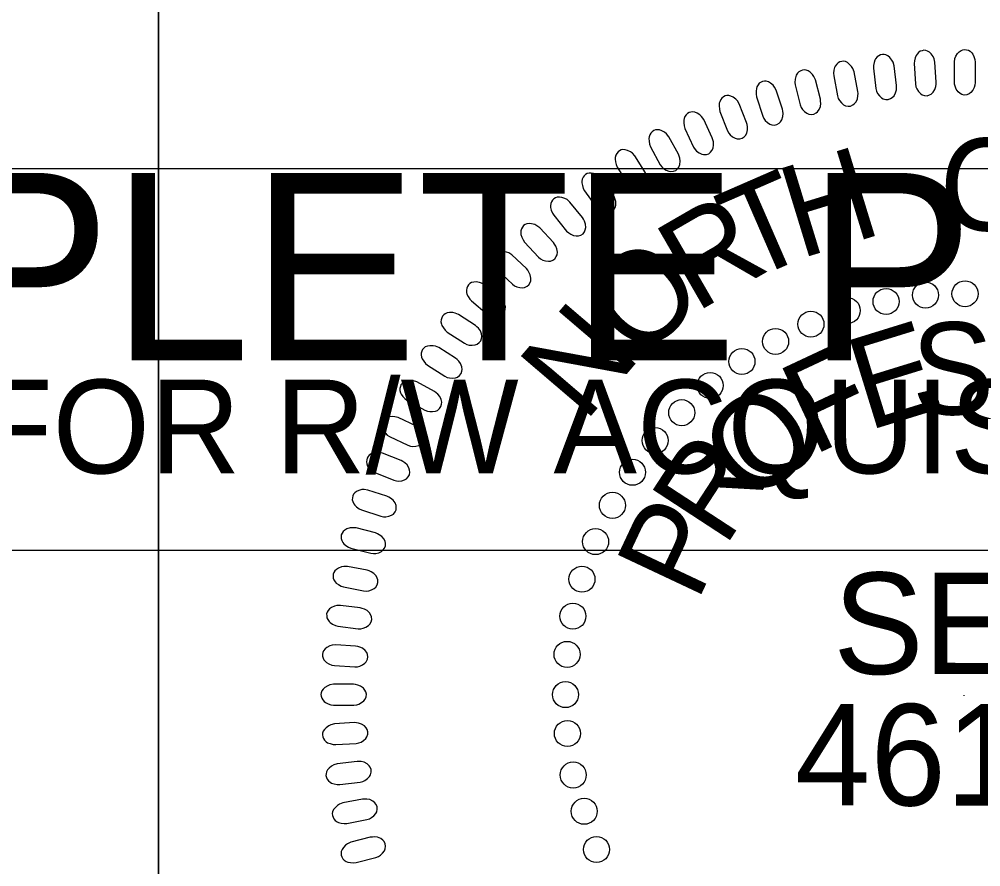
# Model space of a CAD drawing. Extents: x 505602 to 507548, y 483109 to 484209.
# Drawn here: x 507160.5 to 507219.7, y 484083.1 to 484135.2 of the extents above; entities that cross this region are included whole.
import ezdxf

# ---------------------------------------------------------------- set-up
doc = ezdxf.new("R2010")
doc.units = 0
for name, color, linetype in [('Sheet PE Seal Cell', 7, 'Continuous'), ('Sheet Profile CELL', 7, 'Continuous'), ('Sheet Sticker Incomplete CELL', 7, 'Continuous')]:
    doc.layers.add(name, color=color, linetype=linetype)

msp = doc.modelspace()

# ---------------------------------------------------------------- linework, layer by layer
at = {"layer": 'Sheet PE Seal Cell'}
msp.add_line((507218.627, 484093.626), (507218.627, 484093.58), dxfattribs=at)
for points in [[(507214.482, 484131.1), (507214.328, 484132.317), (507214.264, 484132.531), (507214.194, 484132.662), (507214.062, 484132.817), (507213.952, 484132.913), (507213.831, 484132.978), (507213.722, 484133.005), (507213.608, 484133.011), (507213.499, 484132.977), (507213.384, 484132.932), (507213.288, 484132.86), (507213.196, 484132.748), (507213.147, 484132.661), (507213.099, 484132.504), (507213.062, 484132.319), (507213.06, 484132.158), (507213.21, 484130.91), (507213.253, 484130.745), (507213.315, 484130.612), (507213.424, 484130.464), (507213.553, 484130.34), (507213.659, 484130.273), (507213.822, 484130.233), (507213.973, 484130.232), (507214.116, 484130.29), (507214.214, 484130.353), (507214.328, 484130.468), (507214.425, 484130.651), (507214.469, 484130.837), (507214.483, 484130.97)], [(507216.92, 484131.303), (507216.843, 484132.527), (507216.792, 484132.744), (507216.731, 484132.88), (507216.609, 484133.043), (507216.505, 484133.146), (507216.388, 484133.218), (507216.281, 484133.252), (507216.168, 484133.264), (507216.057, 484133.237), (507215.94, 484133.2), (507215.839, 484133.134), (507215.741, 484133.028), (507215.687, 484132.945), (507215.628, 484132.791), (507215.58, 484132.608), (507215.568, 484132.448), (507215.639, 484131.193), (507215.671, 484131.025), (507215.725, 484130.889), (507215.824, 484130.735), (507215.945, 484130.603), (507216.047, 484130.529), (507216.208, 484130.479), (507216.358, 484130.468), (507216.505, 484130.518), (507216.606, 484130.574), (507216.727, 484130.682), (507216.835, 484130.858), (507216.891, 484131.042), (507216.913, 484131.173)], [(507218.035, 484131.312), (507218.035, 484132.539), (507218.073, 484132.758), (507218.126, 484132.898), (507218.238, 484133.067), (507218.335, 484133.177), (507218.447, 484133.257), (507218.551, 484133.297), (507218.664, 484133.317), (507218.776, 484133.296), (507218.896, 484133.267), (507219, 484133.207), (507219.105, 484133.107), (507219.165, 484133.027), (507219.232, 484132.877), (507219.292, 484132.698), (507219.314, 484132.538), (507219.321, 484131.282), (507219.299, 484131.112), (507219.253, 484130.973), (507219.164, 484130.813), (507219.052, 484130.673), (507218.954, 484130.594), (507218.797, 484130.534), (507218.648, 484130.514), (507218.499, 484130.554), (507218.394, 484130.604), (507218.266, 484130.703), (507218.147, 484130.873), (507218.08, 484131.053), (507218.05, 484131.183)], [(507212.1, 484130.733), (507211.871, 484131.937), (507211.793, 484132.146), (507211.716, 484132.273), (507211.574, 484132.419), (507211.458, 484132.508), (507211.333, 484132.566), (507211.223, 484132.585), (507211.109, 484132.584), (507211.002, 484132.544), (507210.891, 484132.492), (507210.799, 484132.414), (507210.714, 484132.296), (507210.671, 484132.206), (507210.633, 484132.046), (507210.608, 484131.859), (507210.615, 484131.698), (507210.843, 484130.463), (507210.897, 484130.3), (507210.967, 484130.171), (507211.085, 484130.031), (507211.221, 484129.915), (507211.332, 484129.855), (507211.497, 484129.826), (507211.647, 484129.834), (507211.787, 484129.901), (507211.881, 484129.97), (507211.987, 484130.091), (507212.073, 484130.28), (507212.105, 484130.469), (507212.11, 484130.602)], [(507209.795, 484130.26), (507209.491, 484131.448), (507209.4, 484131.651), (507209.314, 484131.774), (507209.164, 484131.91), (507209.042, 484131.992), (507208.914, 484132.042), (507208.802, 484132.055), (507208.689, 484132.046), (507208.585, 484131.999), (507208.477, 484131.94), (507208.39, 484131.856), (507208.314, 484131.734), (507208.276, 484131.642), (507208.247, 484131.48), (507208.234, 484131.291), (507208.252, 484131.131), (507208.557, 484129.912), (507208.621, 484129.753), (507208.699, 484129.629), (507208.826, 484129.497), (507208.969, 484129.389), (507209.083, 484129.337), (507209.25, 484129.317), (507209.4, 484129.335), (507209.535, 484129.411), (507209.624, 484129.485), (507209.722, 484129.613), (507209.795, 484129.807), (507209.816, 484129.998), (507209.813, 484130.13)], [(507207.461, 484129.639), (507207.083, 484130.806), (507206.98, 484131.003), (507206.887, 484131.12), (507206.728, 484131.247), (507206.602, 484131.321), (507206.47, 484131.362), (507206.358, 484131.368), (507206.246, 484131.353), (507206.145, 484131.299), (507206.041, 484131.234), (507205.96, 484131.145), (507205.891, 484131.017), (507205.859, 484130.923), (507205.84, 484130.76), (507205.839, 484130.57), (507205.867, 484130.411), (507206.248, 484129.214), (507206.322, 484129.06), (507206.407, 484128.941), (507206.542, 484128.817), (507206.692, 484128.719), (507206.809, 484128.673), (507206.977, 484128.664), (507207.125, 484128.692), (507207.255, 484128.776), (507207.339, 484128.856), (507207.429, 484128.989), (507207.49, 484129.188), (507207.499, 484129.379), (507207.487, 484129.512)], [(507205.261, 484128.823), (507204.809, 484129.964), (507204.694, 484130.154), (507204.594, 484130.265), (507204.427, 484130.381), (507204.297, 484130.448), (507204.163, 484130.48), (507204.051, 484130.479), (507203.94, 484130.456), (507203.843, 484130.396), (507203.742, 484130.325), (507203.667, 484130.231), (507203.606, 484130.099), (507203.58, 484130.003), (507203.572, 484129.839), (507203.583, 484129.65), (507203.621, 484129.494), (507204.076, 484128.322), (507204.159, 484128.173), (507204.253, 484128.06), (507204.395, 484127.944), (507204.55, 484127.856), (507204.67, 484127.817), (507204.838, 484127.819), (507204.984, 484127.856), (507205.108, 484127.948), (507205.187, 484128.033), (507205.269, 484128.172), (507205.318, 484128.374), (507205.314, 484128.566), (507205.295, 484128.697)], [(507203.143, 484127.89), (507202.621, 484129), (507202.494, 484129.183), (507202.387, 484129.287), (507202.214, 484129.394), (507202.079, 484129.451), (507201.944, 484129.475), (507201.832, 484129.467), (507201.722, 484129.437), (507201.629, 484129.371), (507201.534, 484129.294), (507201.464, 484129.195), (507201.412, 484129.06), (507201.392, 484128.963), (507201.395, 484128.799), (507201.417, 484128.61), (507201.464, 484128.457), (507201.993, 484127.317), (507202.085, 484127.172), (507202.185, 484127.065), (507202.334, 484126.959), (507202.495, 484126.88), (507202.617, 484126.85), (507202.784, 484126.862), (507202.928, 484126.908), (507203.046, 484127.008), (507203.12, 484127.097), (507203.192, 484127.241), (507203.229, 484127.445), (507203.213, 484127.637), (507203.185, 484127.767)], [(507201.06, 484126.876), (507200.469, 484127.952), (507200.331, 484128.126), (507200.218, 484128.223), (507200.038, 484128.318), (507199.9, 484128.367), (507199.764, 484128.383), (507199.653, 484128.368), (507199.545, 484128.331), (507199.456, 484128.26), (507199.366, 484128.176), (507199.303, 484128.073), (507199.259, 484127.935), (507199.245, 484127.836), (507199.258, 484127.673), (507199.292, 484127.487), (507199.349, 484127.336), (507199.948, 484126.231), (507200.049, 484126.094), (507200.156, 484125.993), (507200.311, 484125.896), (507200.477, 484125.828), (507200.6, 484125.804), (507200.767, 484125.827), (507200.907, 484125.882), (507201.019, 484125.989), (507201.087, 484126.083), (507201.15, 484126.232), (507201.173, 484126.438), (507201.146, 484126.628), (507201.109, 484126.756)], [(507199.043, 484125.734), (507198.386, 484126.77), (507198.237, 484126.936), (507198.118, 484127.025), (507197.933, 484127.109), (507197.792, 484127.149), (507197.655, 484127.157), (507197.544, 484127.134), (507197.439, 484127.091), (507197.355, 484127.014), (507197.27, 484126.925), (507197.214, 484126.819), (507197.179, 484126.678), (507197.171, 484126.579), (507197.194, 484126.416), (507197.24, 484126.233), (507197.306, 484126.085), (507197.973, 484125.02), (507198.083, 484124.889), (507198.196, 484124.795), (507198.357, 484124.709), (507198.526, 484124.651), (507198.651, 484124.635), (507198.816, 484124.669), (507198.952, 484124.732), (507199.058, 484124.846), (507199.119, 484124.945), (507199.173, 484125.096), (507199.183, 484125.304), (507199.144, 484125.492), (507199.1, 484125.617)], [(507197.042, 484124.38), (507196.321, 484125.372), (507196.162, 484125.528), (507196.038, 484125.611), (507195.847, 484125.682), (507195.704, 484125.713), (507195.567, 484125.712), (507195.458, 484125.683), (507195.356, 484125.633), (507195.277, 484125.551), (507195.198, 484125.457), (507195.149, 484125.347), (507195.122, 484125.204), (507195.121, 484125.105), (507195.155, 484124.944), (507195.211, 484124.764), (507195.287, 484124.622), (507196.019, 484123.6), (507196.137, 484123.476), (507196.255, 484123.389), (507196.421, 484123.313), (507196.594, 484123.266), (507196.72, 484123.258), (507196.882, 484123.302), (507197.015, 484123.374), (507197.112, 484123.494), (507197.167, 484123.596), (507197.212, 484123.751), (507197.209, 484123.959), (507197.158, 484124.144), (507197.106, 484124.266)], [(507195.162, 484122.991), (507194.38, 484123.936), (507194.212, 484124.081), (507194.082, 484124.156), (507193.888, 484124.215), (507193.743, 484124.238), (507193.606, 484124.228), (507193.5, 484124.191), (507193.401, 484124.135), (507193.327, 484124.048), (507193.254, 484123.949), (507193.211, 484123.837), (507193.194, 484123.693), (507193.199, 484123.593), (507193.242, 484123.435), (507193.31, 484123.259), (507193.395, 484123.121), (507194.189, 484122.148), (507194.315, 484122.032), (507194.439, 484121.953), (507194.609, 484121.887), (507194.785, 484121.851), (507194.911, 484121.851), (507195.07, 484121.905), (507195.198, 484121.986), (507195.287, 484122.112), (507195.336, 484122.216), (507195.371, 484122.374), (507195.354, 484122.581), (507195.292, 484122.762), (507195.232, 484122.881)], [(507193.374, 484121.452), (507192.535, 484122.346), (507192.357, 484122.481), (507192.223, 484122.547), (507192.025, 484122.594), (507191.88, 484122.607), (507191.744, 484122.589), (507191.64, 484122.546), (507191.544, 484122.484), (507191.476, 484122.393), (507191.409, 484122.289), (507191.374, 484122.174), (507191.366, 484122.029), (507191.377, 484121.93), (507191.43, 484121.775), (507191.51, 484121.604), (507191.602, 484121.472), (507192.457, 484120.55), (507192.589, 484120.442), (507192.717, 484120.371), (507192.892, 484120.316), (507193.07, 484120.291), (507193.195, 484120.299), (507193.35, 484120.363), (507193.473, 484120.451), (507193.554, 484120.582), (507193.597, 484120.69), (507193.622, 484120.85), (507193.593, 484121.055), (507193.518, 484121.232), (507193.452, 484121.347)], [(507191.712, 484119.843), (507190.818, 484120.682), (507190.632, 484120.805), (507190.495, 484120.863), (507190.294, 484120.898), (507190.148, 484120.902), (507190.013, 484120.875), (507189.912, 484120.826), (507189.821, 484120.758), (507189.759, 484120.663), (507189.699, 484120.555), (507189.67, 484120.438), (507189.671, 484120.293), (507189.689, 484120.195), (507189.751, 484120.043), (507189.841, 484119.877), (507189.942, 484119.751), (507190.853, 484118.885), (507190.992, 484118.785), (507191.124, 484118.722), (507191.302, 484118.679), (507191.48, 484118.665), (507191.605, 484118.68), (507191.757, 484118.754), (507191.873, 484118.849), (507191.946, 484118.986), (507191.982, 484119.096), (507191.996, 484119.257), (507191.955, 484119.461), (507191.87, 484119.632), (507191.796, 484119.742)], [(507190.098, 484118.056), (507189.154, 484118.838), (507188.96, 484118.949), (507188.82, 484118.998), (507188.617, 484119.02), (507188.471, 484119.015), (507188.339, 484118.979), (507188.241, 484118.924), (507188.154, 484118.85), (507188.098, 484118.751), (507188.045, 484118.64), (507188.024, 484118.521), (507188.034, 484118.377), (507188.057, 484118.28), (507188.13, 484118.133), (507188.23, 484117.972), (507188.338, 484117.853), (507189.301, 484117.046), (507189.446, 484116.955), (507189.583, 484116.901), (507189.763, 484116.868), (507189.941, 484116.866), (507190.065, 484116.89), (507190.211, 484116.973), (507190.322, 484117.075), (507190.387, 484117.215), (507190.415, 484117.328), (507190.419, 484117.489), (507190.365, 484117.689), (507190.27, 484117.856), (507190.188, 484117.961)], [(507188.574, 484116.353), (507187.544, 484117.019), (507187.339, 484117.107), (507187.193, 484117.139), (507186.99, 484117.137), (507186.845, 484117.115), (507186.718, 484117.063), (507186.628, 484116.997), (507186.55, 484116.914), (507186.505, 484116.809), (507186.466, 484116.692), (507186.459, 484116.572), (507186.486, 484116.43), (507186.52, 484116.336), (507186.61, 484116.199), (507186.728, 484116.05), (507186.85, 484115.945), (507187.901, 484115.257), (507188.056, 484115.184), (507188.197, 484115.146), (507188.38, 484115.135), (507188.558, 484115.153), (507188.678, 484115.192), (507188.813, 484115.291), (507188.911, 484115.405), (507188.959, 484115.553), (507188.974, 484115.668), (507188.959, 484115.829), (507188.882, 484116.021), (507188.767, 484116.175), (507188.674, 484116.27)], [(507187.359, 484114.331), (507186.324, 484114.988), (507186.119, 484115.074), (507185.973, 484115.105), (507185.769, 484115.102), (507185.625, 484115.078), (507185.497, 484115.027), (507185.408, 484114.959), (507185.33, 484114.875), (507185.287, 484114.769), (507185.249, 484114.653), (507185.243, 484114.532), (507185.271, 484114.391), (507185.306, 484114.297), (507185.397, 484114.16), (507185.516, 484114.014), (507185.639, 484113.909), (507186.696, 484113.229), (507186.851, 484113.157), (507186.993, 484113.12), (507187.175, 484113.111), (507187.353, 484113.13), (507187.473, 484113.169), (507187.607, 484113.27), (507187.704, 484113.386), (507187.751, 484113.533), (507187.765, 484113.648), (507187.749, 484113.809), (507187.67, 484114), (507187.554, 484114.154), (507187.461, 484114.249)], [(507186.056, 484112.281), (507184.981, 484112.873), (507184.771, 484112.946), (507184.623, 484112.968), (507184.421, 484112.951), (507184.277, 484112.918), (507184.154, 484112.859), (507184.069, 484112.786), (507183.997, 484112.698), (507183.961, 484112.59), (507183.929, 484112.471), (507183.931, 484112.35), (507183.968, 484112.211), (507184.009, 484112.12), (507184.107, 484111.988), (507184.236, 484111.85), (507184.365, 484111.753), (507185.462, 484111.141), (507185.621, 484111.078), (507185.765, 484111.051), (507185.949, 484111.052), (507186.125, 484111.083), (507186.242, 484111.13), (507186.37, 484111.239), (507186.459, 484111.36), (507186.496, 484111.51), (507186.503, 484111.625), (507186.477, 484111.786), (507186.386, 484111.971), (507186.262, 484112.117), (507186.162, 484112.206)], [(507184.947, 484110.157), (507183.837, 484110.68), (507183.623, 484110.74), (507183.474, 484110.752), (507183.273, 484110.723), (507183.132, 484110.682), (507183.013, 484110.614), (507182.932, 484110.537), (507182.866, 484110.444), (507182.836, 484110.334), (507182.813, 484110.212), (507182.822, 484110.093), (507182.868, 484109.956), (507182.914, 484109.868), (507183.021, 484109.743), (507183.158, 484109.612), (507183.292, 484109.523), (507184.427, 484108.981), (507184.589, 484108.93), (507184.735, 484108.911), (507184.917, 484108.924), (507185.091, 484108.966), (507185.205, 484109.02), (507185.326, 484109.136), (507185.408, 484109.263), (507185.435, 484109.415), (507185.435, 484109.532), (507185.399, 484109.689), (507185.297, 484109.869), (507185.163, 484110.006), (507185.058, 484110.089)], [(507184.008, 484108.039), (507182.868, 484108.491), (507182.65, 484108.536), (507182.501, 484108.54), (507182.302, 484108.498), (507182.164, 484108.448), (507182.049, 484108.373), (507181.973, 484108.29), (507181.913, 484108.193), (507181.89, 484108.082), (507181.874, 484107.959), (507181.891, 484107.84), (507181.945, 484107.707), (507181.997, 484107.621), (507182.112, 484107.504), (507182.257, 484107.382), (507182.396, 484107.302), (507183.562, 484106.832), (507183.727, 484106.791), (507183.874, 484106.781), (507184.055, 484106.806), (507184.226, 484106.858), (507184.337, 484106.919), (507184.451, 484107.043), (507184.524, 484107.175), (507184.542, 484107.328), (507184.534, 484107.444), (507184.488, 484107.599), (507184.374, 484107.772), (507184.232, 484107.901), (507184.122, 484107.977)], [(507183.132, 484105.85), (507181.965, 484106.229), (507181.745, 484106.261), (507181.596, 484106.255), (507181.4, 484106.201), (507181.265, 484106.142), (507181.155, 484106.06), (507181.085, 484105.973), (507181.032, 484105.872), (507181.016, 484105.76), (507181.007, 484105.637), (507181.032, 484105.519), (507181.094, 484105.388), (507181.152, 484105.307), (507181.273, 484105.196), (507181.425, 484105.084), (507181.57, 484105.013), (507182.763, 484104.617), (507182.931, 484104.586), (507183.078, 484104.586), (507183.257, 484104.622), (507183.424, 484104.686), (507183.531, 484104.753), (507183.636, 484104.883), (507183.701, 484105.02), (507183.709, 484105.175), (507183.694, 484105.289), (507183.639, 484105.441), (507183.515, 484105.607), (507183.364, 484105.727), (507183.25, 484105.795)], [(507182.428, 484103.594), (507181.239, 484103.899), (507181.018, 484103.917), (507180.869, 484103.902), (507180.677, 484103.836), (507180.547, 484103.769), (507180.441, 484103.68), (507180.377, 484103.589), (507180.329, 484103.485), (507180.321, 484103.372), (507180.32, 484103.248), (507180.352, 484103.132), (507180.423, 484103.006), (507180.485, 484102.928), (507180.613, 484102.825), (507180.772, 484102.723), (507180.921, 484102.661), (507182.136, 484102.341), (507182.306, 484102.321), (507182.452, 484102.329), (507182.629, 484102.377), (507182.792, 484102.45), (507182.894, 484102.525), (507182.991, 484102.662), (507183.047, 484102.802), (507183.046, 484102.956), (507183.024, 484103.07), (507182.959, 484103.218), (507182.825, 484103.376), (507182.667, 484103.486), (507182.549, 484103.547)], [(507181.916, 484101.298), (507180.712, 484101.528), (507180.489, 484101.533), (507180.342, 484101.508), (507180.154, 484101.429), (507180.028, 484101.355), (507179.929, 484101.259), (507179.87, 484101.164), (507179.829, 484101.058), (507179.828, 484100.944), (507179.835, 484100.821), (507179.874, 484100.707), (507179.952, 484100.586), (507180.019, 484100.512), (507180.154, 484100.417), (507180.319, 484100.325), (507180.471, 484100.273), (507181.705, 484100.029), (507181.875, 484100.02), (507182.021, 484100.038), (507182.194, 484100.096), (507182.352, 484100.18), (507182.449, 484100.261), (507182.537, 484100.403), (507182.585, 484100.547), (507182.574, 484100.701), (507182.544, 484100.813), (507182.47, 484100.957), (507182.327, 484101.106), (507182.162, 484101.206), (507182.041, 484101.26)], [(507181.496, 484098.984), (507180.279, 484099.138), (507180.057, 484099.129), (507179.911, 484099.095), (507179.729, 484099.004), (507179.608, 484098.922), (507179.515, 484098.821), (507179.462, 484098.722), (507179.428, 484098.613), (507179.434, 484098.499), (507179.449, 484098.377), (507179.495, 484098.266), (507179.581, 484098.149), (507179.653, 484098.08), (507179.792, 484097.994), (507179.963, 484097.912), (507180.118, 484097.87), (507181.364, 484097.705), (507181.535, 484097.706), (507181.679, 484097.733), (507181.848, 484097.801), (507182.001, 484097.896), (507182.093, 484097.982), (507182.172, 484098.13), (507182.211, 484098.276), (507182.189, 484098.429), (507182.153, 484098.539), (507182.07, 484098.678), (507181.917, 484098.818), (507181.747, 484098.907), (507181.623, 484098.953)], [(507181.21, 484096.64), (507179.985, 484096.717), (507179.764, 484096.694), (507179.621, 484096.651), (507179.445, 484096.55), (507179.329, 484096.459), (507179.242, 484096.353), (507179.196, 484096.251), (507179.169, 484096.14), (507179.182, 484096.027), (507179.205, 484095.905), (507179.257, 484095.797), (507179.35, 484095.687), (507179.426, 484095.622), (507179.571, 484095.545), (507179.746, 484095.474), (507179.904, 484095.442), (507181.158, 484095.355), (507181.329, 484095.366), (507181.471, 484095.403), (507181.636, 484095.482), (507181.782, 484095.585), (507181.868, 484095.677), (507181.937, 484095.83), (507181.967, 484095.978), (507181.936, 484096.129), (507181.893, 484096.237), (507181.802, 484096.371), (507181.64, 484096.5), (507181.465, 484096.579), (507181.338, 484096.617)], [(507181.08, 484094.289), (507179.853, 484094.289), (507179.634, 484094.252), (507179.493, 484094.2), (507179.324, 484094.088), (507179.214, 484093.991), (507179.135, 484093.878), (507179.095, 484093.774), (507179.075, 484093.662), (507179.095, 484093.55), (507179.124, 484093.43), (507179.184, 484093.326), (507179.284, 484093.221), (507179.364, 484093.161), (507179.513, 484093.093), (507179.693, 484093.034), (507179.852, 484093.011), (507181.109, 484093.003), (507181.278, 484093.026), (507181.418, 484093.071), (507181.577, 484093.16), (507181.717, 484093.272), (507181.797, 484093.37), (507181.857, 484093.526), (507181.877, 484093.676), (507181.837, 484093.826), (507181.787, 484093.93), (507181.688, 484094.058), (507181.518, 484094.177), (507181.339, 484094.244), (507181.209, 484094.274)], [(507181.132, 484091.931), (507179.907, 484091.855), (507179.691, 484091.804), (507179.555, 484091.743), (507179.392, 484091.62), (507179.288, 484091.517), (507179.216, 484091.4), (507179.183, 484091.293), (507179.171, 484091.179), (507179.198, 484091.069), (507179.235, 484090.951), (507179.3, 484090.851), (507179.407, 484090.753), (507179.49, 484090.698), (507179.644, 484090.64), (507179.827, 484090.592), (507179.987, 484090.579), (507181.242, 484090.65), (507181.41, 484090.684), (507181.546, 484090.737), (507181.7, 484090.837), (507181.832, 484090.957), (507181.906, 484091.059), (507181.956, 484091.219), (507181.966, 484091.37), (507181.917, 484091.517), (507181.861, 484091.618), (507181.753, 484091.738), (507181.577, 484091.847), (507181.393, 484091.903), (507181.262, 484091.925)], [(507181.297, 484089.55), (507180.079, 484089.397), (507179.867, 484089.332), (507179.734, 484089.264), (507179.58, 484089.131), (507179.483, 484089.021), (507179.418, 484088.899), (507179.392, 484088.791), (507179.386, 484088.676), (507179.42, 484088.568), (507179.465, 484088.453), (507179.537, 484088.356), (507179.649, 484088.266), (507179.736, 484088.216), (507179.892, 484088.168), (507180.078, 484088.131), (507180.239, 484088.129), (507181.487, 484088.278), (507181.652, 484088.322), (507181.785, 484088.384), (507181.932, 484088.493), (507182.057, 484088.621), (507182.124, 484088.728), (507182.164, 484088.891), (507182.164, 484089.042), (507182.106, 484089.185), (507182.044, 484089.283), (507181.929, 484089.397), (507181.746, 484089.494), (507181.559, 484089.538), (507181.427, 484089.551)], [(507181.63, 484087.225), (507180.425, 484086.995), (507180.216, 484086.918), (507180.089, 484086.841), (507179.943, 484086.698), (507179.853, 484086.582), (507179.796, 484086.457), (507179.777, 484086.347), (507179.778, 484086.233), (507179.819, 484086.127), (507179.871, 484086.015), (507179.948, 484085.923), (507180.067, 484085.839), (507180.156, 484085.795), (507180.316, 484085.757), (507180.503, 484085.732), (507180.664, 484085.74), (507181.9, 484085.968), (507182.062, 484086.022), (507182.191, 484086.092), (507182.33, 484086.209), (507182.447, 484086.346), (507182.507, 484086.456), (507182.537, 484086.621), (507182.528, 484086.773), (507182.461, 484086.911), (507182.393, 484087.005), (507182.271, 484087.111), (507182.082, 484087.197), (507181.892, 484087.23), (507181.76, 484087.234)], [(507182.11, 484084.884), (507180.921, 484084.579), (507180.718, 484084.488), (507180.595, 484084.404), (507180.459, 484084.252), (507180.377, 484084.131), (507180.328, 484084.002), (507180.315, 484083.891), (507180.324, 484083.778), (507180.371, 484083.674), (507180.429, 484083.566), (507180.513, 484083.479), (507180.636, 484083.403), (507180.728, 484083.364), (507180.89, 484083.336), (507181.079, 484083.323), (507181.239, 484083.341), (507182.458, 484083.646), (507182.617, 484083.71), (507182.74, 484083.788), (507182.873, 484083.915), (507182.98, 484084.058), (507183.033, 484084.171), (507183.052, 484084.339), (507183.034, 484084.489), (507182.959, 484084.623), (507182.884, 484084.712), (507182.756, 484084.811), (507182.562, 484084.884), (507182.371, 484084.905), (507182.239, 484084.901)]]:
    msp.add_lwpolyline(points, close=True, dxfattribs=at)
for centre in [(507216.263, 484118.216), (507218.692, 484118.295), (507213.835, 484117.819), (507211.446, 484117.262), (507209.216, 484116.426), (507207.041, 484115.365), (507204.971, 484114.131), (507203.019, 484112.658), (507201.267, 484110.985), (507199.634, 484109.272), (507198.24, 484107.321), (507197.005, 484105.29), (507195.969, 484103.059), (507195.132, 484100.749), (507194.574, 484098.478), (507194.215, 484096.128), (507194.119, 484093.653), (507194.237, 484091.263), (507194.595, 484088.713), (507195.271, 484086.482), (507196.027, 484084.132)]:
    msp.add_circle(centre, 0.801, dxfattribs=at)
at = {"layer": 'Sheet Profile CELL'}
msp.add_line((507169.08, 484158.662), (507169.08, 484046.212), dxfattribs=at)
for points in [[(507069.03, 484158.662), (507169.08, 484158.662), (507169.08, 484046.162), (507069.03, 484046.162)], [(507169.08, 484158.662), (507269.08, 484158.662), (507269.08, 484046.162), (507169.08, 484046.162)]]:
    msp.add_lwpolyline(points, close=True, dxfattribs=at)
at = {"layer": 'Sheet Sticker Incomplete CELL'}
msp.add_lwpolyline([(507095.597, 484102.505), (507095.597, 484126.005), (507242.597, 484126.005), (507242.597, 484102.505)], close=True, dxfattribs=at)

# ---------------------------------------------------------------- texts
at = {"layer": 'Sheet PE Seal Cell'}
for s, height, rotation, p in [('C', 5.669, 357.58768, (507217.01, 484122.307)), ('H', 5.669, 17.05575, (507208.505, 484120.423)), ('T', 5.669, 23.5451, (507205.326, 484119.013)), ('R', 5.669, 30.03446, (507202.105, 484117.094)), ('O', 5.669, 43.01317, (507198.63, 484114.066)), ('N', 5.669, 49.50253, (507195.283, 484110.311)), ('E', 5.669, 17.16862, (507212.701, 484109.854)), ('S', 5.669, 1.28903, (507215.468, 484110.814)), ('F', 5.669, 25.10842, (507209.311, 484108.316)), ('O', 5.669, 40.98802, (507205.614, 484105.177)), ('R', 5.669, 56.86761, (507203.9, 484102.631)), ('P', 5.669, 64.80741, (507202.214, 484099.269)), ('SEAL', 6.2363, 359.98136, (507210.585, 484094.92)), ('46155', 6.2363, 359.98136, (507208.236, 484086.841))]:
    msp.add_text(s, height=height, rotation=rotation, dxfattribs=at).set_placement(p)
at = {"layer": 'Sheet Sticker Incomplete CELL'}
for s, height, p in [('INCOMPLETE PLANS', 11.52, (507104.547, 484114.205)), ('DO NOT USE FOR R/W ACQUISITION', 5.76, (507107.797, 484107.255))]:
    msp.add_text(s, height=height, dxfattribs=at).set_placement(p)

doc.saveas('drawing.dxf')
